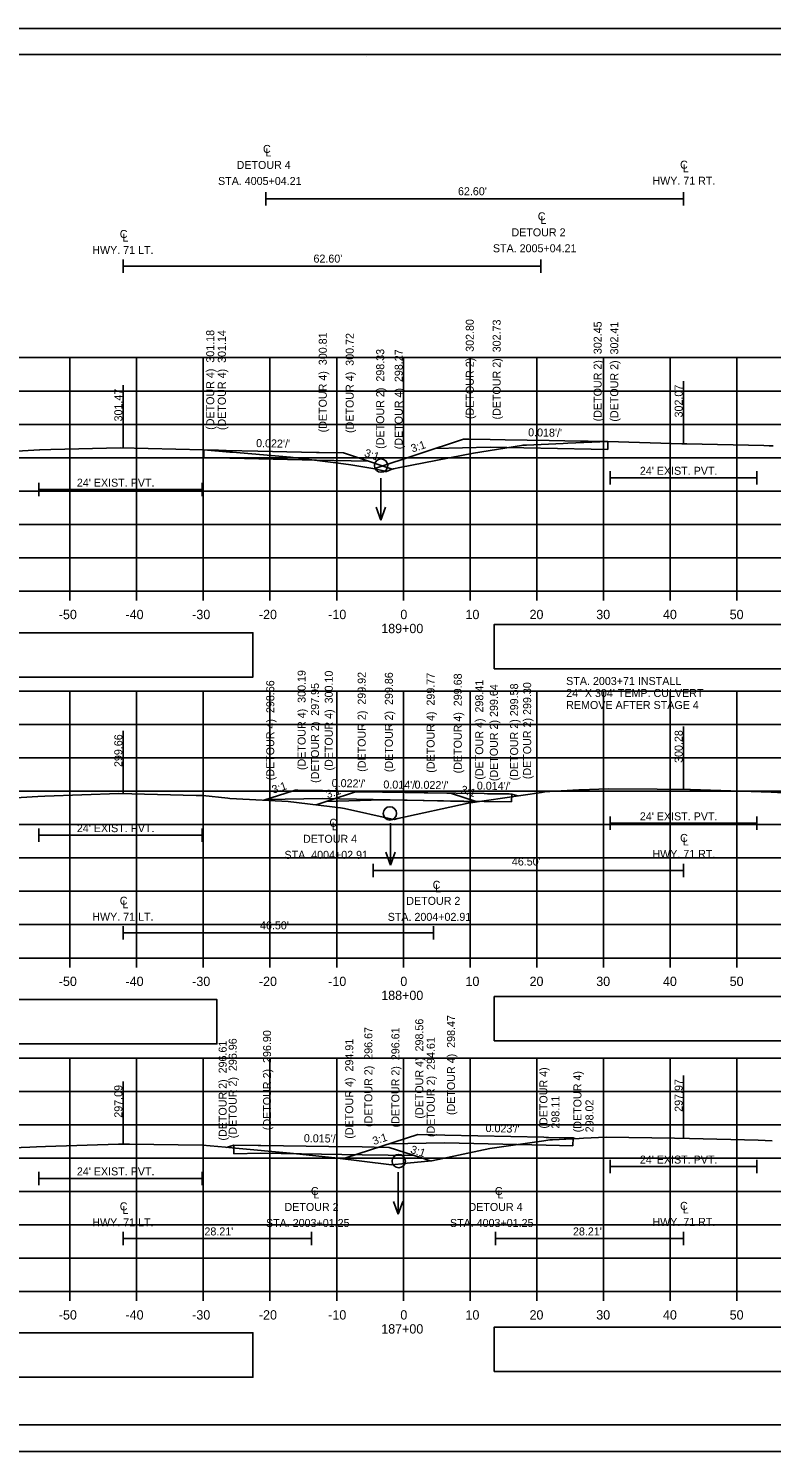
# Model space of a CAD drawing. Extents: x 285 to 4233, y -659 to 3710.
# Drawn here: x 1167.5 to 1278.9, y 2732.3 to 2945.6 of the extents above; entities that cross this region are included whole.
import ezdxf

# ---------------------------------------------------------------- set-up
doc = ezdxf.new("R2010")
doc.units = 0
for name, color, linetype in [('R_Alt Surface', 7, 'Continuous'), ('R_Axis', 7, 'Continuous'), ('R_Axis Annot', 7, 'Continuous'), ('R_Border', 7, 'Continuous'), ('R_Detour', 7, 'Continuous'), ('R_Detour Annot', 7, 'Continuous'), ('R_Exist Surface', 7, 'Continuous'), ('R_Grid', 7, 'Continuous'), ('R_No Plot', 7, 'Continuous'), ('R_Water', 7, 'Continuous'), ('R_Water Annot', 7, 'Continuous'), ('R_Xsect Elev', 7, 'Continuous')]:
    doc.layers.add(name, color=color, linetype=linetype)

msp = doc.modelspace()

# ---------------------------------------------------------------- linework, layer by layer
at = {"layer": 'R_Alt Surface'}
msp.add_line((1239.91, 2830.84), (1239.9, 2829.68), dxfattribs=at)
for points in [[(1203.07, 2921.09), (1203.07, 2919.09)], [(1265.68, 2921.09), (1265.68, 2919.09)], [(1265.68, 2920.09), (1203.07, 2920.09)], [(1181.68, 2910.99), (1181.68, 2908.99)], [(1181.68, 2909.99), (1244.28, 2909.99)], [(1244.28, 2910.99), (1244.28, 2908.99)], [(1254.68, 2879.27), (1254.68, 2877.27)], [(1254.68, 2878.27), (1276.68, 2878.27)], [(1276.68, 2879.27), (1276.68, 2877.27)], [(1169.03, 2877.49), (1169.03, 2875.49)], [(1169.03, 2876.49), (1193.53, 2876.49)], [(1193.53, 2877.49), (1193.53, 2875.49)], [(1254.68, 2827.47), (1254.68, 2825.47)], [(1276.68, 2827.47), (1276.68, 2825.47)], [(1169.03, 2825.7), (1169.03, 2823.7)], [(1169.03, 2824.7), (1193.53, 2824.7)], [(1193.53, 2825.7), (1193.53, 2823.7)], [(1254.68, 2826.47), (1276.68, 2826.47)], [(1219.17, 2820.39), (1219.17, 2818.39)], [(1265.68, 2820.39), (1265.68, 2818.39)], [(1265.68, 2819.39), (1219.17, 2819.39)], [(1181.68, 2811.04), (1181.68, 2809.04)], [(1181.68, 2810.04), (1228.18, 2810.04)], [(1228.18, 2811.04), (1228.18, 2809.04)], [(1254.68, 2776.01), (1254.68, 2774.01)], [(1276.68, 2776.01), (1276.68, 2774.01)], [(1169.03, 2774.24), (1169.03, 2772.24)], [(1193.53, 2774.24), (1193.53, 2772.24)], [(1254.68, 2775.01), (1276.68, 2775.01)], [(1169.03, 2773.24), (1193.53, 2773.24)], [(1181.68, 2765.23), (1181.68, 2763.23)], [(1209.89, 2765.23), (1209.89, 2763.23)], [(1237.47, 2765.23), (1237.47, 2763.23)], [(1265.68, 2765.23), (1265.68, 2763.23)], [(1181.68, 2764.23), (1209.89, 2764.23)], [(1265.68, 2764.23), (1237.47, 2764.23)]]:
    msp.add_lwpolyline(points, dxfattribs=at)
at = {"layer": 'R_Axis'}
for p, q in [((1073.68, 2861.27), (1373.68, 2861.27)), ((1173.68, 2859.87), (1173.68, 2861.27)), ((1183.68, 2859.87), (1183.68, 2861.27)), ((1193.68, 2859.87), (1193.68, 2861.27)), ((1203.68, 2859.87), (1203.68, 2861.27)), ((1213.68, 2859.87), (1213.68, 2861.27)), ((1223.68, 2859.87), (1223.68, 2861.27)), ((1233.68, 2859.87), (1233.68, 2861.27)), ((1243.68, 2859.87), (1243.68, 2861.27)), ((1253.68, 2859.87), (1253.68, 2861.27)), ((1263.68, 2859.87), (1263.68, 2861.27)), ((1273.68, 2859.87), (1273.68, 2861.27)), ((1073.68, 2806.27), (1373.68, 2806.27)), ((1173.68, 2804.87), (1173.68, 2806.27)), ((1183.68, 2804.87), (1183.68, 2806.27)), ((1193.68, 2804.87), (1193.68, 2806.27)), ((1203.68, 2804.87), (1203.68, 2806.27)), ((1213.68, 2804.87), (1213.68, 2806.27)), ((1223.68, 2804.87), (1223.68, 2806.27)), ((1233.68, 2804.87), (1233.68, 2806.27)), ((1243.68, 2804.87), (1243.68, 2806.27)), ((1253.68, 2804.87), (1253.68, 2806.27)), ((1263.68, 2804.87), (1263.68, 2806.27)), ((1273.68, 2804.87), (1273.68, 2806.27)), ((1073.68, 2756.27), (1373.68, 2756.27)), ((1173.68, 2754.87), (1173.68, 2756.27)), ((1183.68, 2754.87), (1183.68, 2756.27)), ((1193.68, 2754.87), (1193.68, 2756.27)), ((1203.68, 2754.87), (1203.68, 2756.27)), ((1213.68, 2754.87), (1213.68, 2756.27)), ((1223.68, 2754.87), (1223.68, 2756.27)), ((1233.68, 2754.87), (1233.68, 2756.27)), ((1243.68, 2754.87), (1243.68, 2756.27)), ((1253.68, 2754.87), (1253.68, 2756.27)), ((1263.68, 2754.87), (1263.68, 2756.27)), ((1273.68, 2754.87), (1273.68, 2756.27))]:
    msp.add_line(p, q, dxfattribs=at)
at = {"layer": 'R_Axis Annot'}
for points in [[(1073.44, 2848.38), (1201.13, 2848.38), (1201.13, 2855.03), (1073.44, 2855.03)], [(1237.31, 2849.62), (1377.31, 2849.62), (1377.31, 2856.27), (1237.31, 2856.27)], [(1068.03, 2793.4), (1195.73, 2793.4), (1195.73, 2800.05), (1068.03, 2800.05)], [(1237.31, 2793.84), (1377.31, 2793.84), (1377.31, 2800.49), (1237.31, 2800.49)], [(1073.44, 2743.43), (1201.13, 2743.43), (1201.13, 2750.08), (1073.44, 2750.08)], [(1237.31, 2744.28), (1377.31, 2744.28), (1377.31, 2750.93), (1237.31, 2750.93)]]:
    msp.add_lwpolyline(points, close=True, dxfattribs=at)
at = {"layer": 'R_Border'}
for p, q in [((1065.68, 2941.73), (1381.86, 2941.73)), ((1218.2, 2941.47), (1218.2, 2941.47)), ((1218.2, 2941.47), (1218.2, 2941.47)), ((1381.86, 2736.27), (1065.68, 2736.27))]:
    msp.add_line(p, q, dxfattribs=at)
at = {"layer": 'R_Detour'}
for p, q in [((1193.77, 2882.45), (1193.77, 2881.21)), ((1254.34, 2883.68), (1254.34, 2882.51)), ((1198.24, 2778.23), (1198.27, 2776.9)), ((1249.11, 2779.29), (1249.08, 2778.12))]:
    msp.add_line(p, q, dxfattribs=at)
for points in [[(1193.77, 2882.45), (1195.46, 2882.41), (1195.51, 2882.41), (1195.97, 2882.4), (1197.13, 2882.37), (1201.84, 2882.27), (1208.4, 2882.12), (1210.64, 2882.07), (1211.05, 2882.07), (1214.68, 2881.98), (1217.09, 2881.18), (1222.02, 2879.54)], [(1219.25, 2879.6), (1226.02, 2881.85), (1232.68, 2884.07), (1233.51, 2884.05), (1236.71, 2884), (1238.96, 2883.96), (1245.52, 2883.84), (1250.22, 2883.75), (1251.38, 2883.73), (1251.85, 2883.72), (1251.93, 2883.72), (1254.34, 2883.68)], [(1228.4, 2882.64), (1236.71, 2882.83), (1251.85, 2882.56), (1254.34, 2882.51)], [(1193.77, 2881.21), (1195.51, 2881.24), (1210.64, 2880.91), (1218.43, 2880.74)], [(1202.77, 2829.92), (1207.15, 2831.35), (1207.47, 2831.45), (1207.84, 2831.45), (1211.54, 2831.37), (1220, 2831.18), (1226.81, 2831.04), (1230.17, 2830.96), (1230.88, 2830.95), (1234.73, 2829.68), (1234.74, 2829.68)], [(1210.58, 2829.22), (1212.56, 2829.88), (1216.48, 2831.18), (1217.18, 2831.17), (1220.55, 2831.13), (1227.35, 2831.03), (1235.81, 2830.91), (1236.29, 2830.9), (1239.52, 2830.86), (1239.77, 2830.85), (1239.88, 2830.85), (1239.91, 2830.84), (1240.77, 2830.56)], [(1203.16, 2830.05), (1211.54, 2830.2), (1226.81, 2829.87), (1234.67, 2829.7)], [(1212.17, 2829.75), (1220.55, 2829.96), (1235.81, 2829.74), (1239.9, 2829.68)], [(1214.61, 2776.18), (1215.04, 2776.32), (1225.82, 2779.83), (1228.04, 2779.78), (1229.87, 2779.73), (1244.71, 2779.39), (1245.06, 2779.38), (1245.1, 2779.38), (1245.44, 2779.37), (1247.78, 2779.32), (1249.11, 2779.29), (1249.25, 2779.24), (1249.37, 2779.2)], [(1197.18, 2777.88), (1197.61, 2778.02), (1198.24, 2778.23), (1201.91, 2778.17), (1202.29, 2778.17), (1212.48, 2778.01), (1217.48, 2777.94), (1219.32, 2777.91), (1221.53, 2777.88), (1226.22, 2776.35), (1227.69, 2775.88)], [(1221.53, 2778.43), (1229.87, 2778.57), (1245.06, 2778.22), (1249.08, 2778.12)], [(1198.27, 2776.9), (1202.29, 2777), (1217.48, 2776.77), (1225.3, 2776.65)]]:
    msp.add_lwpolyline(points, dxfattribs=at)
for centre in [(1220.33, 2880.08), (1221.65, 2827.95)]:
    msp.add_circle(centre, 1, dxfattribs=at)
at = {"layer": 'R_Exist Surface'}
for points in [[(1159.77, 2881.9), (1169.12, 2882.46), (1169.16, 2882.46), (1170.81, 2882.5), (1181.29, 2882.75), (1193.69, 2882.45), (1193.77, 2882.45), (1193.78, 2882.45), (1197.64, 2882.11), (1198.05, 2882.08), (1206.77, 2881.34), (1213.95, 2880.47), (1215.79, 2880.19), (1219.38, 2879.58), (1220.43, 2879.33), (1221.02, 2879.18), (1221.17, 2879.22), (1221.87, 2879.49), (1222.2, 2879.61), (1223.13, 2879.79), (1234.2, 2881.93), (1241.38, 2883.1), (1241.59, 2883.14), (1242.11, 2883.16), (1247.64, 2883.4), (1248.31, 2883.43), (1254.34, 2883.68), (1265.41, 2883.35), (1266.19, 2883.33), (1277.73, 2883.08), (1278.5, 2883.06), (1279.09, 2883.03)], [(1160.52, 2829.97), (1168.87, 2830.49), (1169.94, 2830.53), (1181.02, 2830.94), (1192.6, 2830.65), (1193.62, 2830.63), (1197.35, 2830.21), (1197.64, 2830.18), (1198.65, 2830.13), (1206.41, 2829.74), (1214.25, 2828.76), (1214.84, 2828.7), (1222.02, 2827.11), (1222.28, 2827.06), (1222.83, 2827.18), (1233.38, 2829.48), (1244.4, 2831.1), (1244.89, 2831.17), (1246.45, 2831.26), (1249.99, 2831.46), (1250.16, 2831.46), (1254.36, 2831.65), (1254.4, 2831.65), (1261.71, 2831.58), (1266.62, 2831.54), (1266.71, 2831.53), (1278.79, 2831.13), (1288.13, 2830.65)], [(1159.91, 2777.6), (1167.7, 2777.9), (1168.68, 2777.94), (1170.05, 2777.99), (1180.95, 2778.37), (1182.63, 2778.35), (1193.58, 2778.21), (1197.03, 2777.89), (1197.51, 2777.85), (1198.52, 2777.76), (1206.68, 2777.02), (1213.38, 2776.33), (1221.88, 2775.27), (1221.9, 2775.27), (1221.92, 2775.27), (1223.96, 2775.48), (1224.24, 2775.5), (1227.88, 2775.87), (1227.93, 2775.88), (1236.65, 2777.72), (1244.72, 2778.88), (1245.61, 2779), (1246.01, 2779.03), (1250.03, 2779.23), (1250.68, 2779.26), (1254.1, 2779.42), (1264.33, 2779.26), (1266.57, 2779.23), (1276.87, 2778.94), (1278.95, 2778.88)]]:
    msp.add_lwpolyline(points, dxfattribs=at)
at = {"layer": 'R_Grid'}
for p, q in [((1073.68, 2896.27), (1373.68, 2896.27)), ((1173.68, 2861.27), (1173.68, 2896.27)), ((1183.68, 2861.27), (1183.68, 2896.27)), ((1193.68, 2861.27), (1193.68, 2896.27)), ((1203.68, 2861.27), (1203.68, 2896.27)), ((1213.68, 2861.27), (1213.68, 2896.27)), ((1223.68, 2861.27), (1223.68, 2896.27)), ((1233.68, 2861.27), (1233.68, 2896.27)), ((1243.68, 2861.27), (1243.68, 2896.27)), ((1253.68, 2861.27), (1253.68, 2896.27)), ((1263.68, 2861.27), (1263.68, 2896.27)), ((1273.68, 2861.27), (1273.68, 2896.27)), ((1073.68, 2891.27), (1373.68, 2891.27)), ((1073.68, 2886.27), (1373.68, 2886.27)), ((1073.68, 2881.27), (1373.68, 2881.27)), ((1073.68, 2876.27), (1373.68, 2876.27)), ((1073.68, 2871.27), (1373.68, 2871.27)), ((1073.68, 2866.27), (1373.68, 2866.27)), ((1073.68, 2861.27), (1373.68, 2861.27)), ((1073.68, 2846.27), (1373.68, 2846.27)), ((1173.68, 2806.27), (1173.68, 2846.27)), ((1183.68, 2806.27), (1183.68, 2846.27)), ((1193.68, 2806.27), (1193.68, 2846.27)), ((1203.68, 2806.27), (1203.68, 2846.27)), ((1213.68, 2806.27), (1213.68, 2846.27)), ((1223.68, 2806.27), (1223.68, 2846.27)), ((1233.68, 2806.27), (1233.68, 2846.27)), ((1243.68, 2806.27), (1243.68, 2846.27)), ((1253.68, 2806.27), (1253.68, 2846.27)), ((1263.68, 2806.27), (1263.68, 2846.27)), ((1273.68, 2806.27), (1273.68, 2846.27)), ((1073.68, 2841.27), (1373.68, 2841.27)), ((1073.68, 2836.27), (1373.68, 2836.27)), ((1073.68, 2831.27), (1373.68, 2831.27)), ((1073.68, 2826.27), (1373.68, 2826.27)), ((1073.68, 2821.27), (1373.68, 2821.27)), ((1073.68, 2816.27), (1373.68, 2816.27)), ((1073.68, 2811.27), (1373.68, 2811.27)), ((1073.68, 2806.27), (1373.68, 2806.27)), ((1073.68, 2791.27), (1373.68, 2791.27)), ((1173.68, 2756.27), (1173.68, 2791.27)), ((1183.68, 2756.27), (1183.68, 2791.27)), ((1193.68, 2756.27), (1193.68, 2791.27)), ((1203.68, 2756.27), (1203.68, 2791.27)), ((1213.68, 2756.27), (1213.68, 2791.27)), ((1223.68, 2756.27), (1223.68, 2791.27)), ((1233.68, 2756.27), (1233.68, 2791.27)), ((1243.68, 2756.27), (1243.68, 2791.27)), ((1253.68, 2756.27), (1253.68, 2791.27)), ((1263.68, 2756.27), (1263.68, 2791.27)), ((1273.68, 2756.27), (1273.68, 2791.27)), ((1073.68, 2786.27), (1373.68, 2786.27)), ((1073.68, 2781.27), (1373.68, 2781.27)), ((1073.68, 2776.27), (1373.68, 2776.27)), ((1073.68, 2771.27), (1373.68, 2771.27)), ((1073.68, 2766.27), (1373.68, 2766.27)), ((1073.68, 2761.27), (1373.68, 2761.27)), ((1073.68, 2756.27), (1373.68, 2756.27))]:
    msp.add_line(p, q, dxfattribs=at)
at = {"layer": 'R_No Plot'}
for p, q in [((1053.28, 2945.62), (1386.61, 2945.62)), ((1053.28, 2732.29), (1386.61, 2732.29))]:
    msp.add_line(p, q, dxfattribs=at)
for points in [[(1053.27, 2945.62), (1386.61, 2945.62), (1386.61, 2732.28), (1053.27, 2732.28)], [(1299.6, 2941.73), (1319.22, 2941.73), (1319.22, 2931.85), (1335.33, 2931.85), (1358.53, 2931.85), (1358.65, 2903.69), (1381.86, 2903.69), (1381.86, 2736.27), (1065.68, 2736.27), (1065.68, 2941.73)]]:
    msp.add_lwpolyline(points, close=True, dxfattribs=at)
at = {"layer": 'R_Water'}
msp.add_circle((1222.98, 2775.82), 1, dxfattribs=at)
at = {"layer": 'R_Water Annot'}
for p, q in [((1220.28, 2878.21), (1220.3, 2871.93)), ((1220.3, 2871.93), (1219.59, 2873.85)), ((1220.3, 2871.93), (1220.99, 2873.85)), ((1221.75, 2826.48), (1221.77, 2820.19)), ((1221.77, 2820.19), (1221.06, 2822.12)), ((1221.77, 2820.19), (1222.46, 2822.12)), ((1222.88, 2774.15), (1222.9, 2767.87)), ((1222.9, 2767.87), (1222.19, 2769.79)), ((1222.9, 2767.87), (1223.59, 2769.79))]:
    msp.add_line(p, q, dxfattribs=at)
at = {"layer": 'R_Xsect Elev'}
for p, q in [((1181.68, 2882.74), (1181.68, 2892.16)), ((1265.68, 2883.34), (1265.68, 2892.76)), ((1181.68, 2830.93), (1181.68, 2840.35)), ((1265.68, 2831.55), (1265.68, 2840.97)), ((1265.68, 2779.24), (1265.68, 2788.66)), ((1181.68, 2778.36), (1181.68, 2787.78))]:
    msp.add_line(p, q, dxfattribs=at)

# ---------------------------------------------------------------- texts
at = {"layer": 'R_Alt Surface'}
for s, height, p in [('C', 1.2, (1202.63, 2926.96)), ('L', 1.2, (1203.01, 2926.43)), ('DETOUR 4', 1.199, (1198.68, 2924.56)), ('C', 1.2, (1265.16, 2924.6)), ('L', 1.2, (1265.55, 2924.07)), ('STA. 4005+04.21', 1.1985, (1195.89, 2922.16)), ('HWY. 71 RT.', 1.1985, (1261.01, 2922.2)), ('C', 1.2, (1243.83, 2916.86)), ('L', 1.2, (1244.22, 2916.33)), ('C', 1.2, (1181.16, 2914.21)), ('L', 1.2, (1181.54, 2913.68)), ('DETOUR 2', 1.199, (1239.88, 2914.46)), ('HWY. 71 LT.', 1.1985, (1177.04, 2911.81)), ('STA. 2005+04.21', 1.1985, (1237.1, 2912.07)), ('C', 1.2, (1212.58, 2825.94)), ('DETOUR 4', 1.199, (1208.63, 2823.54)), ('L', 1.2, (1212.96, 2825.41)), ('C', 1.2, (1265.16, 2823.67)), ('HWY. 71 RT.', 1.1985, (1261.01, 2821.27)), ('L', 1.2, (1265.55, 2823.14)), ('STA. 4004+02.91', 1.1985, (1205.85, 2821.14)), ('C', 1.2, (1228.06, 2816.64)), ('L', 1.2, (1228.44, 2816.11)), ('C', 1.2, (1181.16, 2814.26)), ('L', 1.2, (1181.54, 2813.73)), ('DETOUR 2', 1.199, (1224.11, 2814.24)), ('HWY. 71 LT.', 1.1985, (1177.04, 2811.86)), ('STA. 2004+02.91', 1.1985, (1221.33, 2811.84)), ('C', 1.2, (1209.81, 2770.74)), ('L', 1.2, (1210.2, 2770.22)), ('C', 1.2, (1237.39, 2770.74)), ('L', 1.2, (1237.78, 2770.22)), ('C', 1.2, (1181.16, 2768.44)), ('DETOUR 2', 1.199, (1205.86, 2768.35)), ('DETOUR 4', 1.199, (1233.44, 2768.35)), ('C', 1.2, (1265.16, 2768.51)), ('L', 1.2, (1265.55, 2767.98)), ('HWY. 71 LT.', 1.1985, (1177.04, 2766.04)), ('L', 1.2, (1181.54, 2767.91)), ('STA. 2003+01.25', 1.1985, (1203.08, 2765.95)), ('STA. 4003+01.25', 1.1985, (1230.66, 2765.95)), ('HWY. 71 RT.', 1.1985, (1261.01, 2766.11))]:
    msp.add_text(s, height=height, dxfattribs=at).set_placement(p)
at = {"layer": 'R_Axis Annot'}
for s, p in [('-50', (1172.02, 2857.07)), ('-40', (1182.02, 2857.07)), ('-30', (1192.02, 2857.07)), ('-20', (1202.02, 2857.07)), ('-10', (1212.41, 2857.07)), ('0', (1223.22, 2857.07)), ('10', (1232.99, 2857.07)), ('20', (1242.59, 2857.07)), ('30', (1252.59, 2857.07)), ('40', (1262.59, 2857.07)), ('50', (1272.59, 2857.07)), ('189+00', (1220.36, 2854.97)), ('-50', (1172.02, 2802.07)), ('-40', (1182.02, 2802.07)), ('-30', (1192.02, 2802.07)), ('-20', (1202.02, 2802.07)), ('-10', (1212.41, 2802.07)), ('0', (1223.22, 2802.07)), ('10', (1232.99, 2802.07)), ('20', (1242.59, 2802.07)), ('30', (1252.59, 2802.07)), ('40', (1262.59, 2802.07)), ('50', (1272.59, 2802.07)), ('188+00', (1220.36, 2799.97)), ('-50', (1172.02, 2752.07)), ('-40', (1182.02, 2752.07)), ('-30', (1192.02, 2752.07)), ('-20', (1202.02, 2752.07)), ('-10', (1212.41, 2752.07)), ('0', (1223.22, 2752.07)), ('10', (1232.99, 2752.07)), ('20', (1242.59, 2752.07)), ('30', (1252.59, 2752.07)), ('40', (1262.59, 2752.07)), ('50', (1272.59, 2752.07)), ('187+00', (1220.36, 2749.97))]:
    msp.add_text(s, height=1.4, dxfattribs=at).set_placement(p)
at = {"layer": 'R_Detour Annot'}
for s, rotation, p in [('(DETOUR 2)  302.80', 90, (1234.23, 2887.07)), ('(DETOUR 2)  302.73', 90, (1238.26, 2887)), ('(DETOUR 2)  302.45', 90, (1253.4, 2886.72)), ('(DETOUR 2)  302.41', 90, (1255.89, 2886.68)), ('(DETOUR 4)  301.18', 90, (1195.32, 2885.45)), ('(DETOUR 4)  301.14', 90, (1197.06, 2885.41)), ('(DETOUR 4)  300.81', 90, (1212.19, 2885.07)), ('(DETOUR 4)  300.72', 90, (1216.23, 2884.98)), ('(DETOUR 2)  298.33', 90, (1220.8, 2882.6)), ('(DETOUR 4)  298.27', 90, (1223.57, 2882.54)), ("0.018'/'", 358.961, (1242.37, 2884.49)), ("0.022'/'", 358.7337, (1201.59, 2882.87)), ('3:1', 341.6021, (1217.72, 2881.5)), ('3:1', 18.4091, (1225.02, 2882.04)), ('(DETOUR 4)  300.19', 90, (1209.02, 2834.45)), ('(DETOUR 4)  300.10', 90, (1213.09, 2834.37)), ('(DETOUR 2)  299.92', 90, (1218.03, 2834.18)), ('(DETOUR 2)  299.86', 90, (1222.1, 2834.13)), ('(DETOUR 4)  299.77', 90, (1228.36, 2834.04)), ('(DETOUR 4)  299.68', 90, (1232.43, 2833.95)), ('(DETOUR 4)  298.66', 90, (1204.32, 2832.92)), ('(DETOUR 2)  297.95', 90, (1211.02, 2832.52)), ('(DETOUR 4)  298.41', 90, (1235.65, 2833)), ('(DETOUR 2) 299.64', 90, (1237.84, 2832.78)), ('(DETOUR 2) 299.58', 90, (1240.88, 2832.89)), ('(DETOUR 2) 299.30', 90, (1242.83, 2833.08)), ("0.022'/'", 358.7638, (1212.92, 2831.92)), ('3:1', 18.0476, (1204.18, 2830.91)), ('3:1', 18.4178, (1212.31, 2830.19)), ("0.014'/'", 359.1838, (1220.67, 2831.69)), ("0.022'/'", 358.7624, (1225.34, 2831.67)), ('3:1', 341.7619, (1232.17, 2831.05)), ("0.014'/'", 359.1801, (1234.68, 2831.52)), ('(DETOUR 4)  298.56', 90, (1226.66, 2782.19)), ('(DETOUR 4)  298.47', 90, (1231.42, 2782.73)), ('(DETOUR 2)  296.90', 90, (1203.84, 2780.46)), ('(DETOUR 2)  296.67', 90, (1219.03, 2780.94)), ('(DETOUR 2)  296.61', 90, (1223.08, 2780.88)), ('(DETOUR 2)  296.61', 90, (1197.18, 2778.9)), ('(DETOUR 2)  296.96', 90, (1198.69, 2779.25)), ('(DETOUR 4)  294.91', 90, (1216.16, 2779.18)), ('(DETOUR 2)  294.61', 90, (1228.38, 2779.42)), ('(DETOUR 4)', 90, (1245.27, 2780.7)), ('(DETOUR 4)', 90, (1250.37, 2780.14)), ('298.11', 90, (1247.07, 2780.7)), ('298.02', 90, (1252.17, 2780.14)), ("0.015'/'", 359.1314, (1208.75, 2778.67)), ('3:1', 18.0391, (1219.27, 2778.22)), ("0.023'/'", 358.6722, (1235.99, 2780.19)), ('3:1', 342.0212, (1224.64, 2777.08))]:
    msp.add_text(s, height=1.2, rotation=rotation, dxfattribs=at).set_placement(p)
at = {"layer": 'R_Water'}
for s, p in [("62.60'", (1231.86, 2920.62)), ("62.60'", (1210.2, 2910.52)), ("24' EXIST. PVT.", (1174.73, 2876.93)), ("24' EXIST. PVT.", (1259.13, 2878.71)), ("24' EXIST. PVT.", (1259.13, 2826.91)), ("24' EXIST. PVT.", (1174.73, 2825.14)), ("46.50'", (1239.94, 2820.14)), ("46.50'", (1202.18, 2810.57)), ("24' EXIST. PVT.", (1259.13, 2775.45)), ("24' EXIST. PVT.", (1174.73, 2773.68)), ("28.21'", (1193.85, 2764.68)), ("28.21'", (1249.1, 2764.68))]:
    msp.add_text(s, height=1.2, dxfattribs=at).set_placement(p)
at = {"layer": 'R_Water Annot'}
for s, p in [('STA. 2003+71 INSTALL ', (1248.08, 2847.2)), ('24" X 304\' TEMP. CULVERT', (1248.08, 2845.4)), ('REMOVE AFTER STAGE 4', (1248.08, 2843.6))]:
    msp.add_text(s, height=1.2, dxfattribs=at).set_placement(p)
at = {"layer": 'R_Xsect Elev'}
for s, p in [('301.47', (1181.54, 2886.71)), ('302.07', (1265.54, 2887.31)), ('299.66', (1181.54, 2834.9)), ('300.28', (1265.54, 2835.52)), ('297.09', (1181.54, 2782.33)), ('297.97', (1265.54, 2783.21))]:
    msp.add_text(s, height=1.2, rotation=90, dxfattribs=at).set_placement(p)

doc.saveas('drawing.dxf')
